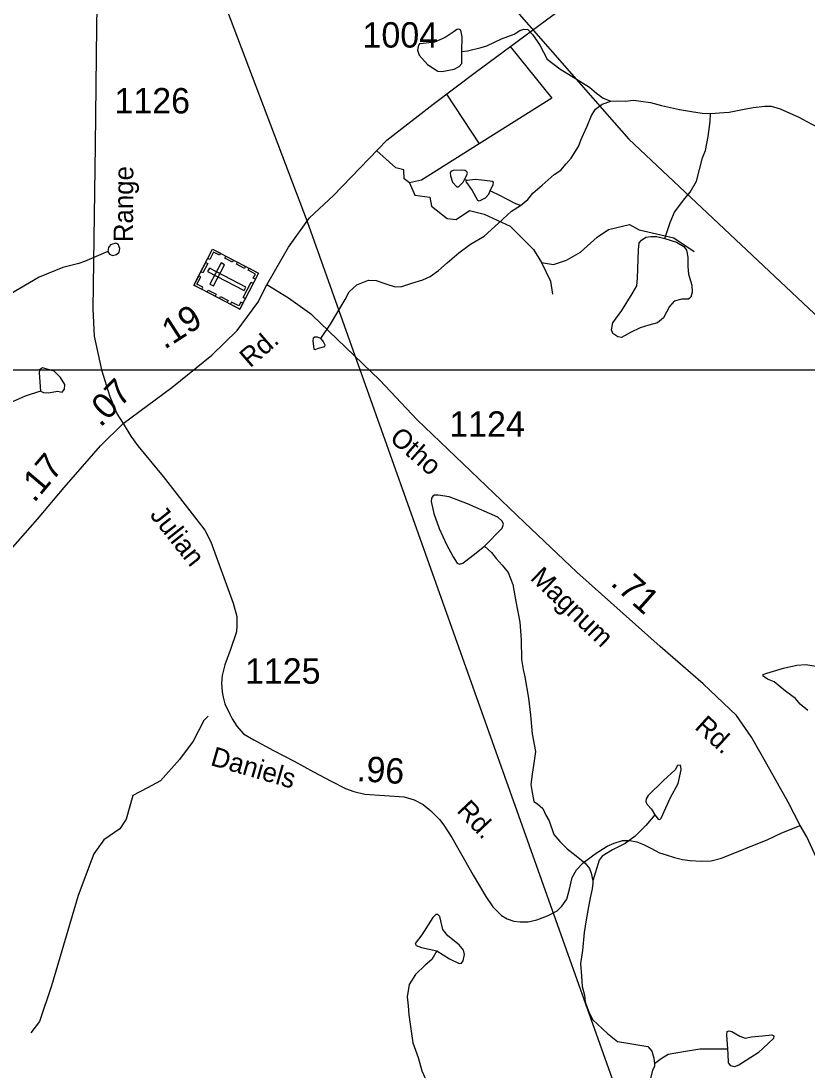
# Model space of a CAD drawing. Extents: x 2056842 to 2160602, y 826753 to 1016856.
# Drawn here: x 2076067 to 2079934, y 883970 to 889134 of the extents above; entities that cross this region are included whole.
import ezdxf

# ---------------------------------------------------------------- set-up
doc = ezdxf.new("R2010")
doc.units = 0
for name, color, linetype in [('Exist Cultural Cemetery CELL', 7, 'Continuous'), ('Exist Hydrographic Creek Single Shore', 7, 'Continuous'), ('Exist Hydrographic Misc Water Feature', 7, 'Continuous'), ('Exist Road Non-System Type 51', 7, 'Continuous'), ('Exist Road Secondary Mileage Hundredths English Label', 7, 'Continuous'), ('Exist Road Secondary Type 51 Attributed', 7, 'Continuous'), ('Exist Road Secondary Type 51 Label', 7, 'Continuous'), ('Exist Road Secondary Type 51 Number Label', 7, 'Continuous'), ('Exist Utilities Electrical Transmission Line', 7, 'Continuous'), ('Map Preparation Inset Cut Line', 7, 'Continuous')]:
    doc.layers.add(name, color=color, linetype=linetype)

msp = doc.modelspace()

# ---------------------------------------------------------------- linework, layer by layer
at = {"layer": 'Exist Cultural Cemetery CELL'}
for points in [[(2076917.3, 887835), (2077009.5, 888011.5), (2077235.2, 887893.6), (2077143, 887717.2)], [(2077047.9, 887991.5), (2077042.7, 887981.4), (2077014.1, 887996.3), (2076995.4, 887960.4), (2076985.5, 887965.5), (2077009.5, 888011.5)], [(2076951.6, 887900.7), (2076975.6, 887946.6), (2076985.7, 887941.3), (2076961.7, 887895.4)], [(2076996.5, 887839.7), (2077013.1, 887831.1), (2077067.6, 887935.4), (2077051, 887944.1)], [(2077107.4, 887947.6), (2077069, 887967.6), (2077074.3, 887977.7), (2077112.7, 887957.6)], [(2077165.8, 887917), (2077127.4, 887937.1), (2077132.7, 887947.2), (2077171.1, 887927.1)], [(2076993.7, 887918.1), (2076985.1, 887901.6), (2077164.8, 887807.7), (2077173.5, 887824.2)], [(2077219.8, 887864.3), (2077209.6, 887869.6), (2077219.8, 887889.1), (2077184, 887907.8), (2077189.2, 887917.7), (2077235.2, 887893.6)], [(2076955.7, 887815), (2076960.9, 887825), (2076932.4, 887840), (2076951.2, 887875.9), (2076941.3, 887881.1), (2076917.3, 887835)], [(2077159.4, 887773.4), (2077198.7, 887848.6), (2077208.8, 887843.3), (2077169.5, 887768.1)], [(2077021.4, 887780.6), (2076983, 887800.7), (2076988.3, 887810.8), (2077026.7, 887790.7)], [(2077081, 887749.5), (2077042.6, 887769.6), (2077047.9, 887779.7), (2077086.3, 887759.6)], [(2077158.3, 887746.5), (2077148.1, 887751.8), (2077137.9, 887732.3), (2077102.1, 887751), (2077096.9, 887741.2), (2077142.9, 887717.1)]]:
    msp.add_lwpolyline(points, close=True, dxfattribs=at)
at = {"layer": 'Exist Hydrographic Creek Single Shore'}
for points in [[(2078347.4, 886551.8), (2078382, 886519.5), (2078404.5, 886490.7), (2078434.5, 886457), (2078463.9, 886422.1), (2078485.8, 886362.3), (2078502, 886278.4), (2078520.3, 886176.6), (2078528.2, 886090.4), (2078529.5, 885994.1), (2078537, 885944.1), (2078545.3, 885908.6), (2078563.8, 885804.4), (2078574, 885720.4), (2078582, 885628), (2078598.2, 885541.7), (2078588.2, 885471.7), (2078582, 885429.2), (2078575.7, 885379.2), (2078580.7, 885349.2), (2078589.4, 885295.4), (2078608.2, 885284.1), (2078634.4, 885261.6), (2078648.2, 885227.9), (2078665.7, 885200.6), (2078687.6, 885133.1), (2078717.8, 885099.3), (2078753.8, 885063.3), (2078797.9, 885027.4), (2078842.2, 884991.6), (2078864.2, 884965.5), (2078871.9, 884943.6), (2078880.2, 884905.4)], [(2079937.6, 885742.8), (2079900.1, 885774), (2079877.6, 885801.5), (2079828.9, 885837.8), (2079772.7, 885884), (2079738.9, 885896.5), (2079718.9, 885911.5), (2079718.9, 885920.3), (2079736.4, 885926.5), (2079817.7, 885950.3), (2079883.9, 885965.3), (2079927.6, 885969.1), (2079977.6, 885960.3)], [(2078880.2, 884905.4), (2078880.4, 884893.7), (2078876.5, 884865.9), (2078866.6, 884821.5), (2078858.8, 884777.6), (2078846.9, 884713.7), (2078836.9, 884651.5), (2078829.3, 884562.2), (2078819.7, 884499.4), (2078824.3, 884435.9), (2078828.1, 884385.9), (2078839.3, 884343.4), (2078842, 884309.9), (2078858.1, 884264.6), (2078879.3, 884223.4), (2078951.8, 884154.6), (2079001.8, 884114.6), (2079053, 884107.3), (2079150.6, 884090.6), (2079170.9, 884066.8), (2079181, 884032.8), (2079183, 884005)], [(2078112.1, 884561.7), (2078087.4, 884519.2), (2078055.6, 884491.2), (2078007.9, 884444.9), (2077976.3, 884394.9), (2077966.2, 884334.7), (2077972, 884290.8), (2077974.6, 884247), (2077994.9, 884108.8), (2078021.2, 884037), (2078039, 883971), (2078061.4, 883919.3)], [(2079183, 884005), (2079183.2, 883992.8), (2079174.2, 883974.6), (2079163, 883927.1)]]:
    msp.add_lwpolyline(points, dxfattribs=at)
at = {"layer": 'Exist Hydrographic Misc Water Feature'}
for points in [[(2078235.2, 888984.1), (2078237.7, 889055.3), (2078231.4, 889089), (2078221.4, 889094), (2078211.5, 889092.7), (2078197.7, 889081.5), (2078154.1, 889052.8), (2078101.7, 889030.3), (2078045.5, 889022.8), (2078028.1, 889021.6), (2078023.1, 889014.1), (2078018.1, 888990.4), (2078025.6, 888965.4), (2078066.8, 888919.2), (2078117.9, 888886.8), (2078137.9, 888885.5), (2078197.7, 888896.8), (2078222.7, 888909.3), (2078235.2, 888925.5), (2078236.4, 888960.4), (2078235.2, 888984.1)], [(2078235.2, 888984.1), (2078263.9, 888986.6), (2078330, 889002.9), (2078359.3, 889011.9), (2078431.3, 889046.1), (2078493.4, 889069.8), (2078521.6, 889086.5), (2078541.5, 889094), (2078560.2, 889091.5), (2078585.2, 889066.5), (2078618.9, 889014.1), (2078655, 888946.7), (2078717.4, 888899.3), (2078863.4, 888808.2), (2078898, 888779.3), (2078930.4, 888753.7), (2078968.3, 888739.8)], [(2078523.8, 888226.1), (2078559.9, 888256.3), (2078585.7, 888286.5), (2078631.4, 888326.6), (2078689.5, 888378.7), (2078723.3, 888400.8), (2078749.1, 888430.9), (2078773.3, 888458.9), (2078809, 888517.2), (2078820.7, 888547.1), (2078834.6, 888577), (2078852.9, 888617.3), (2078874.2, 888669.3), (2078894.1, 888699.5), (2078926.1, 888725.5), (2078968.3, 888739.8)], [(2078968.3, 888739.8), (2079004, 888741.7), (2079040.3, 888739.8), (2079080.5, 888743.9), (2079116.4, 888740), (2079164.4, 888732.3), (2079218.1, 888718.5), (2079306.7, 888698.6), (2079366.1, 888688.8), (2079418.4, 888680.9), (2079459.6, 888678.6)], [(2079234.6, 888064.8), (2079260, 888142.9), (2079281.3, 888194.1), (2079333.5, 888260.7), (2079359.8, 888291.4), (2079391, 888346.3), (2079419.7, 888461.4), (2079434.7, 888497.6), (2079448.4, 888566.3), (2079457.1, 888638.7), (2079459.6, 888678.6)], [(2079459.6, 888678.6), (2079526.3, 888683.5), (2079550.5, 888685.6), (2079625.5, 888699.8), (2079669.2, 888708.6), (2079726.3, 888714.8), (2079757.5, 888714.8), (2079802.4, 888702.3), (2079893.5, 888661.1), (2079955.1, 888628.7), (2079997.5, 888607.5), (2080027.5, 888600), (2080046.5, 888594.9), (2080104.8, 888627.4), (2080137.2, 888633.7), (2080152.2, 888627.4), (2080169.7, 888605), (2080188.4, 888588.7), (2080257, 888573.8), (2080334.3, 888576.3), (2080390.5, 888590)], [(2078249.1, 888354.3), (2078259.1, 888373.1), (2078262.9, 888386.2), (2078259.7, 888392.4), (2078251.6, 888398), (2078236, 888400.5), (2078193.6, 888398.6), (2078181.1, 888393.7), (2078178, 888385.5), (2078179.3, 888373.1), (2078190.5, 888341.9), (2078210.5, 888317.5), (2078218.6, 888318.1), (2078227.9, 888325.6), (2078242.3, 888341.9), (2078249.1, 888354.3)], [(2078259.7, 888349.3), (2078249.1, 888354.3)], [(2078259.7, 888349.3), (2078256, 888345.6), (2078257.2, 888340.6), (2078264.1, 888333.1), (2078287.2, 888300), (2078312.7, 888252.6), (2078319.6, 888248.9), (2078326.5, 888251.4), (2078352, 888264.5), (2078368.3, 888282.6), (2078374.5, 888298.2)], [(2078374.5, 888298.2), (2078390.1, 888330), (2078391.3, 888339.4), (2078385.7, 888344.4), (2078375.7, 888346.8), (2078332.7, 888351.2), (2078300.9, 888353.7), (2078275.3, 888351.8), (2078259.7, 888349.3)], [(2078523.8, 888226.1), (2078501.8, 888234.3), (2078453.1, 888259.5), (2078430, 888272), (2078374.5, 888298.2)], [(2077541.6, 887572.5), (2077590.2, 887643.6), (2077662.3, 887764), (2077681, 887801.4), (2077719.7, 887836.4), (2077777.1, 887858.8), (2077814.5, 887857.6), (2077861.9, 887841.3), (2077908.1, 887826.4), (2077940.5, 887827.6), (2077990.4, 887845.1), (2078044.1, 887860.1), (2078079.4, 887876.8), (2078120.8, 887907), (2078163.1, 887945.2), (2078220.7, 887993.3), (2078278.7, 888035.6), (2078346.2, 888075.7), (2078416.3, 888140.1), (2078480.1, 888198.3), (2078523.8, 888226.1)], [(2079234.6, 888064.8), (2079292, 888046), (2079328.2, 888024.8), (2079340.6, 888006.1), (2079348.1, 887972.4), (2079346.9, 887926.2), (2079350.6, 887888.8), (2079368.1, 887833.9), (2079369.3, 887800.2), (2079363.1, 887776.4), (2079350.6, 887766.5), (2079318.2, 887765.2), (2079280.8, 887756.5), (2079257.1, 887730.3), (2079228.4, 887674.1), (2079198.4, 887649.1), (2079156, 887637.9), (2079112.4, 887624.2), (2079064.9, 887601.7), (2079021.3, 887576.7), (2079002.6, 887580.5), (2078978.9, 887596.7), (2078972.6, 887614.2), (2078978.9, 887649.1), (2079022.5, 887710.3), (2079073.7, 887791.4), (2079097.4, 887831.4), (2079099.9, 887868.8), (2079104.9, 888008.6), (2079107.4, 888042.3), (2079119.8, 888056), (2079141, 888071), (2079166, 888073.5), (2079194.7, 888073.5), (2079234.6, 888064.8)], [(2076494, 887999.4), (2076460.3, 887985.6), (2076379.2, 887950.7), (2076350.5, 887940.7), (2076272, 887922), (2076156.4, 887873.3), (2076013, 887789.7), (2075863.3, 887707.3), (2075752.1, 887601.5), (2075668.6, 887475.4), (2075640.7, 887433.3)], [(2076494, 887999.4), (2076502.7, 887986.9), (2076517.7, 887980.6), (2076536.4, 887985.6), (2076550.1, 887996.9), (2076552.6, 888014.3), (2076545.1, 888035.6), (2076532.7, 888041.8), (2076507.7, 888033.1), (2076496.5, 888020.6), (2076494, 887999.4)], [(2077541.6, 887572.5), (2077525.4, 887578.7), (2077511.6, 887578.7), (2077504.2, 887573.7), (2077502.9, 887561.3), (2077507.9, 887520.1), (2077514.1, 887518.8), (2077530.4, 887525.1), (2077561.5, 887532.6), (2077562.8, 887540), (2077554.1, 887560), (2077541.6, 887572.5)], [(2076163.2, 887313.9), (2076178.1, 887307.6), (2076201.9, 887305.2), (2076246.8, 887312.6), (2076269.2, 887308.9), (2076280.4, 887322.6), (2076281.7, 887346.3), (2076261.7, 887381.3), (2076230.5, 887411.2), (2076171.9, 887427.5), (2076158.2, 887417.5), (2076156.9, 887403.8), (2076163.2, 887313.9)], [(2076163.2, 887313.9), (2076086.9, 887288.6), (2076013.3, 887256.4), (2075951.2, 887236.1), (2075871.4, 887204), (2075787.8, 887187.9), (2075717.2, 887173.4), (2075591.7, 887113.3)], [(2078347.4, 886551.8), (2078434.5, 886639.5), (2078440.8, 886659.5), (2078434.5, 886674.5), (2078412, 886693.2), (2078263.3, 886759.5), (2078173.4, 886793.3), (2078119.6, 886802), (2078100.9, 886802), (2078092.2, 886797), (2078085.9, 886787), (2078084.7, 886770.7), (2078098.4, 886712), (2078124.6, 886638.2), (2078160.9, 886559.5), (2078193.4, 886498.2), (2078212.1, 886467), (2078223.4, 886462), (2078240.8, 886467), (2078292.1, 886507), (2078347.4, 886551.8)], [(2079185.4, 885229.4), (2079201.7, 885208.1), (2079210.4, 885206.9), (2079216.7, 885213.1), (2079239.2, 885264.4), (2079261.7, 885314.4), (2079300.4, 885383.2), (2079314.1, 885450.7), (2079312.9, 885469.4), (2079309.1, 885474.4), (2079296.6, 885471.9), (2079285.4, 885451.9), (2079227.9, 885399.4), (2079151.7, 885324.4), (2079143, 885308.2), (2079141.7, 885294.4), (2079148, 885280.6), (2079169.2, 885256.9), (2079185.4, 885229.4)], [(2079185.4, 885229.4), (2079140.5, 885176.8), (2079089.2, 885124.2), (2079039.3, 885089.2), (2078976.8, 885058), (2078926.8, 885026.7), (2078910.6, 885006.7), (2078880.2, 884905.4)], [(2078112.1, 884561.7), (2078174.6, 884521.7), (2078222.1, 884499.2), (2078234.6, 884500.4), (2078242.1, 884511.7), (2078248.3, 884542.9), (2078243.3, 884564.2), (2078222.1, 884590.4), (2078167.1, 884634.2), (2078142.1, 884665.4), (2078127.1, 884730.4), (2078117.1, 884740.4), (2078108.4, 884740.4), (2078092.2, 884724.2), (2078038.4, 884639.2), (2078005.9, 884596.7), (2078010.9, 884586.7), (2078037.2, 884576.7), (2078112.1, 884561.7)], [(2079544, 884077.3), (2079540.3, 884147.4), (2079541.5, 884163.6), (2079551.5, 884167.4), (2079564, 884164.9), (2079604, 884141.1), (2079630.3, 884132.3), (2079661.5, 884137.3), (2079715.2, 884142.4), (2079761.4, 884148.6), (2079771.4, 884143.6), (2079768.9, 884129.8), (2079744, 884107.3), (2079694, 884059.8), (2079599, 883998.6), (2079576.5, 883991.1), (2079559, 883994.8), (2079547.8, 884009.8), (2079545.3, 884054.8), (2079544, 884077.3)], [(2079544, 884077.3), (2079406.7, 884077.3), (2079327, 884065), (2079250.7, 884051.1), (2079217.1, 884030.6), (2079183, 884005)]]:
    msp.add_lwpolyline(points, dxfattribs=at)
at = {"layer": 'Exist Road Non-System Type 51'}
msp.add_line((2078159.6, 888773.8), (2078321.1, 888530.2), dxfattribs=at)
for points in [[(2078473.9, 889007.9), (2078678.6, 888753.8), (2078321.1, 888530.2)], [(2078321.1, 888530.2), (2078037.3, 888350.6), (2077977.7, 888337.2), (2077952.4, 888358.1), (2077950.9, 888401.3), (2077910.7, 888411.7), (2077816.7, 888495.7)], [(2077977.7, 888337.2), (2078004.5, 888277.6), (2078077.5, 888267.1), (2078086.5, 888223.9), (2078163.9, 888162.8), (2078208.6, 888158.3), (2078274.1, 888201.6), (2078345.6, 888183.7), (2078473.7, 888125.5), (2078587.7, 888010), (2078627.9, 887945.9)], [(2078627.9, 887945.9), (2078686.7, 887936.2), (2078750.8, 887957.1), (2078819.3, 887997.4), (2078901.2, 888070.4), (2078957.1, 888108.4), (2079059.9, 888132.3), (2079107.6, 888106.9), (2079278.9, 888066.7), (2079378.7, 887999.6)], [(2078627.9, 887945.9), (2078671.1, 887853.5), (2078682.3, 887790.2)], [(2076988, 885715.1), (2076965.8, 885694.5), (2076913.6, 885591.7), (2076846.6, 885502.3), (2076752.8, 885396.4), (2076688.7, 885362.1), (2076617.2, 885324.9), (2076583.7, 885209.3), (2076552.4, 885161.6), (2076473.5, 885106.5), (2076424.3, 885037.9), (2076348.3, 884833.7), (2076216.5, 884388.8), (2076157.7, 884213.6), (2076114.5, 884157)]]:
    msp.add_lwpolyline(points, dxfattribs=at)
at = {"layer": 'Exist Road Secondary Type 51 Attributed'}
for points in [[(2076458.8, 891354.1), (2076449.8, 890769.8), (2076451.6, 890002.2), (2076445.3, 889480), (2076438.1, 889106.1), (2076432.4, 888523.7), (2076420.2, 887718.3), (2076427.4, 887583.5), (2076462.6, 887419), (2076503.8, 887287), (2076539.3, 887199.7), (2076569.8, 887153.7)], [(2077276.6, 887836.5), (2077382.6, 888021.6), (2077486.8, 888165.4), (2077603.5, 888275.1), (2077866.7, 888547.4), (2078094.9, 888725.4), (2078301.4, 888880), (2078821.5, 889265.6), (2079260.7, 889566.7), (2079820.3, 889932.5), (2079963.9, 890034.3), (2080152.6, 890168), (2080554.1, 890440.4), (2080687.1, 890562.6), (2080802, 890693.9), (2080833.5, 890752.3)], [(2076569.8, 887153.7), (2076808.8, 887330.7), (2077005.4, 887490.2), (2077130.5, 887612.4), (2077231.8, 887749.5), (2077276.6, 887836.5)], [(2079899.6, 885177.9), (2079840.6, 885292.6), (2079736.3, 885479), (2079660.4, 885611.6), (2079586.6, 885718.2), (2079422.8, 885874.7), (2079211.3, 886058.1), (2078800.9, 886422.5), (2078543.2, 886667), (2078016.6, 887171.6), (2077831.9, 887366.8), (2077497.5, 887689.5), (2077382.8, 887770), (2077276.6, 887836.5)], [(2075979.2, 886491.7), (2076148.3, 886684.1), (2076279.1, 886838.9), (2076457.2, 887044.4), (2076569.8, 887153.7)], [(2076569.8, 887153.7), (2076606.3, 887092.8), (2076641.3, 887044.5), (2076765.8, 886893.8), (2076943.7, 886665.9), (2076970.7, 886629.7), (2077000, 886572.4), (2077109.8, 886270.1), (2077129.2, 886206), (2077128.8, 886161.3), (2077127, 886129.6), (2077097.7, 886042.4), (2077069.6, 885967.7), (2077055.9, 885914.5), (2077052.9, 885876.9), (2077056.5, 885834.5), (2077061.2, 885808.2), (2077069, 885775.9), (2077093.5, 885724.5), (2077104.9, 885701.8), (2077128.2, 885666), (2077162, 885627.7), (2077211.8, 885598.5), (2077309.2, 885545.9), (2077411.4, 885493.3), (2077505.2, 885441.9), (2077592.4, 885394.7), (2077662.9, 885360.1), (2077704.1, 885345.1), (2077758.5, 885330.8), (2077855.4, 885324.3), (2077951.5, 885318.3), (2078001.1, 885303.3), (2078044.7, 885280.6), (2078082.9, 885249.5), (2078125.4, 885207.1), (2078146.3, 885179), (2078185.7, 885118.1), (2078248.4, 885008.2), (2078291.5, 884932.9), (2078353, 884827.7), (2078388.8, 884776.9), (2078431.1, 884734.8), (2078459.4, 884719), (2078491, 884706.4), (2078522.1, 884702.9), (2078561.8, 884703.5), (2078604.8, 884713.6), (2078657.7, 884733.9), (2078705.5, 884758.4), (2078728.2, 884779.9), (2078752.5, 884815.7), (2078764.7, 884864.2), (2078777.8, 884921.5), (2078799.6, 884959.2), (2078833.1, 884993.8), (2078891.6, 885038), (2078951.1, 885075.7), (2078984.8, 885091.2), (2079026.1, 885103.2), (2079062.5, 885104.4), (2079096.6, 885096.6), (2079129.4, 885083.4), (2079165.9, 885065.5), (2079207.4, 885043.4), (2079241.5, 885033.3), (2079281.5, 885020.1), (2079322.1, 885010), (2079358.6, 885005.2), (2079412.9, 885001.6), (2079462.5, 885004), (2079512.7, 885016.5), (2079741.2, 885108.5), (2079807.5, 885140.2), (2079899.6, 885177.9)], [(2079979.1, 885021.4), (2079933, 885121.2), (2079899.6, 885177.9)]]:
    msp.add_lwpolyline(points, dxfattribs=at)
at = {"layer": 'Exist Utilities Electrical Transmission Line'}
for points in [[(2079289.6, 845905.8), (2079948.4, 849305.4), (2079483.2, 855866.2), (2080101, 858353.8), (2081583.8, 864201.8), (2082616, 868304.1), (2080660.7, 871519), (2079505, 873046.5), (2077150, 875999.6), (2076168.7, 877076.1), (2079417.8, 882691.3), (2077477.1, 888146.6), (2075950.7, 892161.6), (2073748.3, 895216.6), (2070106.7, 900031.7)], [(2070228.8, 900032.1), (2072358.2, 897262.8), (2073244.3, 896042.6), (2073834.2, 895260.3), (2077530.5, 890329.4), (2077620.9, 890191.7), (2078985.5, 888634.2), (2079057.9, 888552.5), (2080356.6, 887331.2), (2080736.5, 886973.8)]]:
    msp.add_lwpolyline(points, dxfattribs=at)
at = {"layer": 'Map Preparation Inset Cut Line'}
msp.add_lwpolyline([(2075837.6, 899339.2), (2086885.8, 899339.2), (2086885.8, 887416.1), (2075837.6, 887416.1), (2075837.6, 899339.2)], dxfattribs=at)

# ---------------------------------------------------------------- texts
at = {"layer": 'Exist Road Secondary Mileage Hundredths English Label'}
for s, rotation, p in [('.19', 32.8117, (2076773.2, 887515.8)), ('.07', 45.8348, (2076458.3, 887132)), ('.17', 49.7835, (2076131.5, 886761.1)), ('.71', 318.3923, (2078962.3, 886362.8)), ('.96', 356.1695, (2077716.5, 885396.3))]:
    msp.add_text(s, height=125, rotation=rotation, dxfattribs=at).set_placement(p)
at = {"layer": 'Exist Road Secondary Type 51 Label'}
for s, rotation, p in [('Range', 89.6551, (2076617.4, 888045.7)), ('Rd.', 40.9782, (2077194.1, 887424.9)), ('Otho', 318.7661, (2077875.1, 887073.9)), ('Julian', 308.4021, (2076697, 886703.2)), ('Magnum', 316.2727, (2078567.5, 886389.5)), ('Rd.', 317.7475, (2079376.3, 885656)), ('Daniels', 343.9111, (2076994.4, 885475.3)), ('Rd.', 313.3324, (2078205.8, 885247.5))]:
    msp.add_text(s, height=95, rotation=rotation, dxfattribs=at).set_placement(p)
at = {"layer": 'Exist Road Secondary Type 51 Number Label'}
for s, p in [('1004', (2077747.1, 889002.9)), ('1126', (2076526.5, 888679.2)), ('1124', (2078173.8, 887089.2)), ('1125', (2077168.7, 885874.5))]:
    msp.add_text(s, height=125, dxfattribs=at).set_placement(p)

doc.saveas('drawing.dxf')
